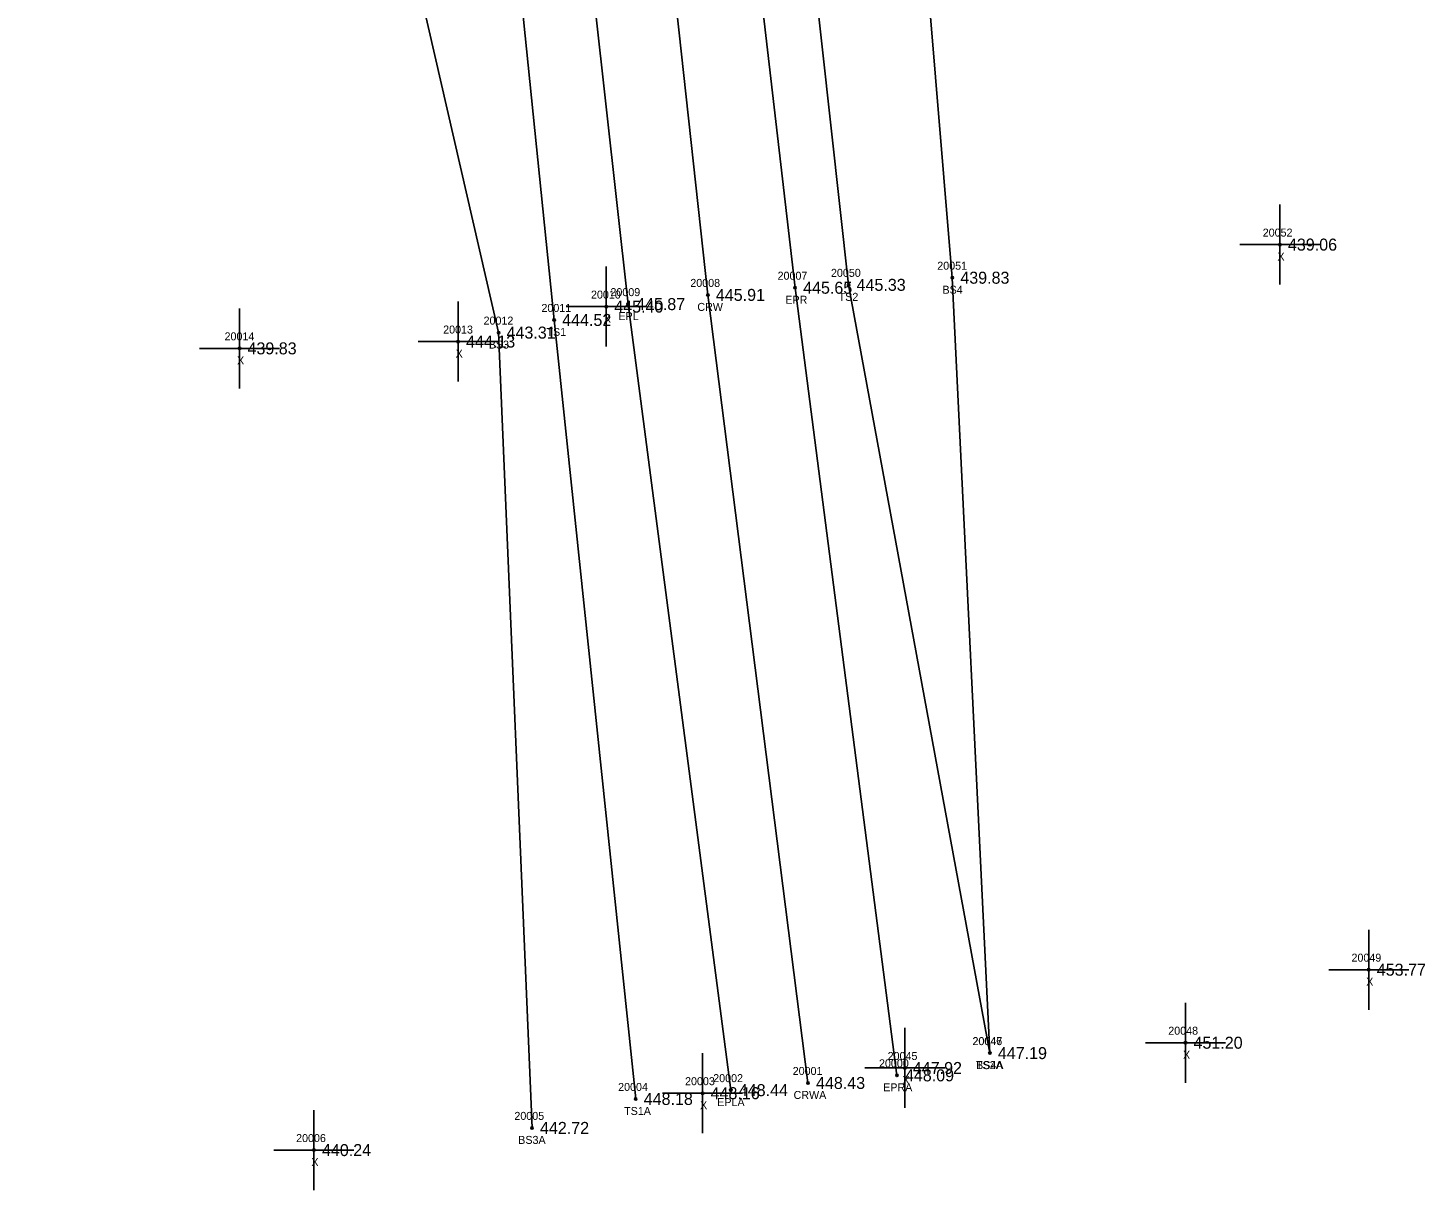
# Model space of a CAD drawing. Extents: x 1858461 to 1858936, y 1147060 to 1148183.
# Drawn here: x 1858651.8 to 1858826.3, y 1147059.8 to 1147205.1 of the extents above; entities that cross this region are included whole.
import ezdxf

# ---------------------------------------------------------------- set-up
doc = ezdxf.new("R2010")
doc.units = 0
for name, color, linetype in [('RD_DTM_BkLn1', 7, 'Continuous'), ('RD_DTM_BkLn2', 7, 'Continuous'), ('RD_DTM_BkLn_txCode', 7, 'Continuous'), ('RD_EX_Misc', 7, 'Continuous'), ('RD_EX_Misc_txCode', 7, 'Continuous'), ('RD_EX_Road', 7, 'Continuous'), ('RD_EX_Road_txCode', 7, 'Continuous'), ('RD_EX_TX_Misc_ELEV', 7, 'Continuous'), ('RD_EX_TX_Road_ELEV', 7, 'Continuous'), ('RD_HC_Survey_ELEV', 7, 'Continuous'), ('RD_HC_Survey_txCode', 7, 'Continuous'), ('RD_SMD_Locator', 7, 'Continuous')]:
    doc.layers.add(name, color=color, linetype=linetype)

msp = doc.modelspace()

# ---------------------------------------------------------------- linework, layer by layer
at = {"layer": 'RD_DTM_BkLn1'}
msp.add_lwpolyline([(1858749.22, 1147073.22), (1858736.71, 1147171.73), (1858725.84, 1147271.15), (1858713.42, 1147369.59), (1858701.55, 1147469.39), (1858689.32, 1147570.79)], dxfattribs=at)
at = {"layer": 'RD_DTM_BkLn2'}
for points in [[(1858771.94, 1147076.95), (1858767.25, 1147173.88), (1858758.88, 1147274.75), (1858748.81, 1147373.06), (1858739.11, 1147481.44), (1858733.31, 1147573.26), (1858722.73, 1147591.49), (1858706.35, 1147596.83)], [(1858714.74, 1147067.6), (1858710.56, 1147167.02), (1858688.24, 1147264.23), (1858669.68, 1147349.51), (1858651.77, 1147379.27), (1858656.32, 1147386.54), (1858661.34, 1147469.11), (1858657.4, 1147555.08), (1858671.87, 1147580.02)], [(1858771.94, 1147076.95), (1858754.29, 1147172.99), (1858743.32, 1147272.09), (1858729.94, 1147370.14), (1858717.88, 1147470.38), (1858711.02, 1147558.86), (1858710.29, 1147569.23), (1858703.02, 1147572.69)], [(1858727.7, 1147071.22), (1858717.51, 1147168.6), (1858707.4, 1147267.83), (1858698.1, 1147368.78), (1858685.2, 1147467.75), (1858675.58, 1147560.05), (1858676.79, 1147568.87)]]:
    msp.add_lwpolyline(points, dxfattribs=at)
at = {"layer": 'RD_EX_Misc'}
for p, q in [((1858808.18, 1147173.02), (1858808.18, 1147183.02)), ((1858803.18, 1147178.02), (1858813.18, 1147178.02)), ((1858724.02, 1147165.27), (1858724.02, 1147175.27)), ((1858705.51, 1147160.9), (1858705.51, 1147170.9)), ((1858678.2, 1147160.05), (1858678.2, 1147170.05)), ((1858719.02, 1147170.27), (1858729.02, 1147170.27)), ((1858700.51, 1147165.9), (1858710.51, 1147165.9)), ((1858673.2, 1147165.05), (1858683.2, 1147165.05)), ((1858819.28, 1147082.38), (1858819.28, 1147092.38)), ((1858814.28, 1147087.38), (1858824.28, 1147087.38)), ((1858796.38, 1147073.25), (1858796.38, 1147083.25)), ((1858761.32, 1147070.09), (1858761.32, 1147080.09)), ((1858791.38, 1147078.25), (1858801.38, 1147078.25)), ((1858736.05, 1147066.94), (1858736.05, 1147076.94)), ((1858756.32, 1147075.09), (1858766.32, 1147075.09)), ((1858731.05, 1147071.94), (1858741.05, 1147071.94)), ((1858687.5, 1147059.83), (1858687.5, 1147069.83)), ((1858682.5, 1147064.83), (1858692.5, 1147064.83))]:
    msp.add_line(p, q, dxfattribs=at)
at = {"layer": 'RD_EX_Road'}
for points in [[(1858739.58, 1147072.32), (1858726.74, 1147170.58), (1858715.7, 1147269.68), (1858703.76, 1147368.69), (1858691.45, 1147468.11), (1858680.5, 1147569.65), (1858689.32, 1147570.79)], [(1858760.33, 1147074.17), (1858747.61, 1147172.63), (1858736.08, 1147271.97), (1858724.51, 1147372.2), (1858712.86, 1147470.38), (1858700.06, 1147571.96), (1858689.32, 1147570.79)]]:
    msp.add_lwpolyline(points, dxfattribs=at)
at = {"layer": 'RD_SMD_Locator'}
for centre in [(1858808.18, 1147178.02), (1858747.61, 1147172.63), (1858754.29, 1147172.99), (1858767.25, 1147173.88), (1858726.74, 1147170.58), (1858736.71, 1147171.73), (1858724.02, 1147170.27), (1858717.51, 1147168.6), (1858705.51, 1147165.9), (1858710.56, 1147167.02), (1858678.2, 1147165.05), (1858819.28, 1147087.38), (1858796.38, 1147078.25), (1858771.94, 1147076.95), (1858771.94, 1147076.95), (1858761.32, 1147075.09), (1858749.22, 1147073.22), (1858760.33, 1147074.17), (1858727.7, 1147071.22), (1858736.05, 1147071.94), (1858739.58, 1147072.32), (1858714.74, 1147067.6), (1858687.5, 1147064.83)]:
    msp.add_circle(centre, 0.15, dxfattribs=at)

# ---------------------------------------------------------------- texts
at = {"layer": 'RD_DTM_BkLn_txCode'}
for s, p in [('20050', (1858752.09, 1147173.99)), ('20051', (1858765.37, 1147174.88)), ('BS4', (1858766.02, 1147171.88)), ('TS2', (1858753.05, 1147170.99)), ('20012', (1858708.69, 1147168.02)), ('20011', (1858715.92, 1147169.6)), ('TS1', (1858716.55, 1147166.6)), ('BS3', (1858709.33, 1147165.02)), ('20046', (1858769.76, 1147077.95)), ('20047', (1858769.78, 1147077.95)), ('TS2A', (1858770.21, 1147074.95)), ('BS4A', (1858770.22, 1147074.95)), ('20004', (1858725.5, 1147072.22)), ('20005', (1858712.54, 1147068.6)), ('TS1A', (1858726.25, 1147069.22)), ('BS3A', (1858713.02, 1147065.6))]:
    msp.add_text(s, height=1, dxfattribs=at).set_placement(p)
at = {"layer": 'RD_EX_Misc_txCode'}
for s, p in [('20052', (1858806.03, 1147179.02)), ('X', (1858807.87, 1147176.02)), ('20010', (1858722.11, 1147171.27)), ('X', (1858723.71, 1147168.27)), ('20013', (1858703.64, 1147166.9)), ('20014', (1858676.33, 1147166.05)), ('X', (1858677.89, 1147163.05)), ('X', (1858705.2, 1147163.9)), ('20049', (1858817.12, 1147088.38)), ('X', (1858818.96, 1147085.38)), ('20048', (1858794.23, 1147079.25)), ('20045', (1858759.17, 1147076.09)), ('X', (1858796.07, 1147076.25)), ('20003', (1858733.86, 1147072.94)), ('X', (1858761.01, 1147073.09)), ('X', (1858735.74, 1147069.94)), ('20006', (1858685.27, 1147065.83)), ('X', (1858687.18, 1147062.83))]:
    msp.add_text(s, height=1, dxfattribs=at).set_placement(p)
at = {"layer": 'RD_EX_Road_txCode'}
for s, p in [('20007', (1858745.42, 1147173.63)), ('20009', (1858724.54, 1147171.58)), ('EPR', (1858746.39, 1147170.63)), ('EPL', (1858725.53, 1147168.58)), ('20000', (1858758.09, 1147075.17)), ('20002', (1858737.38, 1147073.32)), ('EPRA', (1858758.61, 1147072.17)), ('EPLA', (1858737.88, 1147070.32))]:
    msp.add_text(s, height=1, dxfattribs=at).set_placement(p)
at = {"layer": 'RD_EX_TX_Misc_ELEV'}
for s, p in [('439.06', (1858809.18, 1147177.27)), ('439.83', (1858768.25, 1147173.13)), ('445.33', (1858755.29, 1147172.24)), ('445.40', (1858725.02, 1147169.52)), ('444.52', (1858718.51, 1147167.85)), ('443.31', (1858711.56, 1147166.27)), ('439.83', (1858679.2, 1147164.3)), ('444.13', (1858706.51, 1147165.15)), ('453.77', (1858820.28, 1147086.63)), ('451.20', (1858797.38, 1147077.5)), ('447.19', (1858772.94, 1147076.2)), ('447.19', (1858772.94, 1147076.2)), ('447.92', (1858762.32, 1147074.34)), ('448.18', (1858728.7, 1147070.47)), ('448.16', (1858737.05, 1147071.19)), ('442.72', (1858715.74, 1147066.85)), ('440.24', (1858688.5, 1147064.08))]:
    msp.add_text(s, height=1.5, dxfattribs=at).set_placement(p)
at = {"layer": 'RD_EX_TX_Road_ELEV'}
for s, p in [('445.65', (1858748.61, 1147171.88)), ('445.87', (1858727.74, 1147169.83)), ('448.09', (1858761.33, 1147073.42)), ('448.44', (1858740.58, 1147071.57))]:
    msp.add_text(s, height=1.5, dxfattribs=at).set_placement(p)
at = {"layer": 'RD_HC_Survey_ELEV'}
for s, p in [('445.91', (1858737.71, 1147170.98)), ('448.43', (1858750.22, 1147072.47))]:
    msp.add_text(s, height=1.5, dxfattribs=at).set_placement(p)
at = {"layer": 'RD_HC_Survey_txCode'}
for s, p in [('20008', (1858734.52, 1147172.73)), ('CRW', (1858735.4, 1147169.73)), ('20001', (1858747.31, 1147074.22)), ('CRWA', (1858747.42, 1147071.22))]:
    msp.add_text(s, height=1, dxfattribs=at).set_placement(p)

doc.saveas('drawing.dxf')
